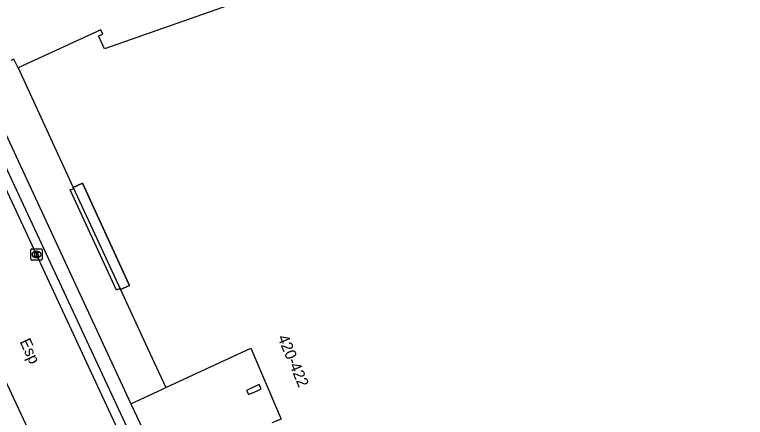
# Model space of a CAD drawing. Extents: x 161389 to 162585, y 388479 to 389761.
# Drawn here: x 162015.4 to 162080.2, y 388829.4 to 388865.1 of the extents above; entities that cross this region are included whole.
import ezdxf

# ---------------------------------------------------------------- set-up
doc = ezdxf.new("R2010")
doc.units = 0
for name, color, linetype in [('IMGEO_Groenvoorziening', 7, 'Continuous'), ('IMGEO_Kolk', 7, 'Continuous'), ('IMGEO_Openbare_ruimte_label', 7, 'Continuous'), ('IMGEO_Pand', 7, 'Continuous'), ('IMGEO_Pand_nummerreeks', 7, 'Continuous'), ('IMGEO_Pand_overbouw', 7, 'Continuous'), ('IMGEO_Rijbaan_lokaal_gesloten', 7, 'Continuous'), ('IMGEO_Voetpad_open', 7, 'Continuous')]:
    doc.layers.add(name, color=color, linetype=linetype)

msp = doc.modelspace()

# ---------------------------------------------------------------- linework, layer by layer
at = {"layer": 'IMGEO_Groenvoorziening'}
for points in [[(162015.754, 388860.392), (162015.389, 388861.182), (162015.139, 388861.066)], [(162024.832, 388840.744), (162024.788, 388840.84), (162024.491, 388840.692), (162020.384, 388849.595), (162020.686, 388849.713), (162020.642, 388849.809)]]:
    msp.add_lwpolyline(points, dxfattribs=at)
at = {"layer": 'IMGEO_Kolk'}
for p, q in [((162016.891, 388843.437), (162016.891, 388844.289)), ((162016.966, 388844.363), (162017.818, 388844.363)), ((162017.892, 388844.289), (162017.892, 388843.437)), ((162017.402, 388843.583), (162017.377, 388843.583)), ((162017.379, 388844.143), (162017.404, 388844.143)), ((162017.818, 388843.363), (162016.966, 388843.363))]:
    msp.add_line(p, q, dxfattribs=at)
for points in [[(162016.891, 388843.437), (162016.891, 388844.289)], [(162016.966, 388844.363), (162017.818, 388844.363)], [(162017.892, 388844.289), (162017.892, 388843.437)], [(162017.212, 388844.063), (162017.335, 388844.063), (162017.335, 388843.912), (162017.465, 388844.063), (162017.629, 388844.063), (162017.483, 388843.912), (162017.636, 388843.663), (162017.484, 388843.663), (162017.399, 388843.827), (162017.335, 388843.76), (162017.335, 388843.663), (162017.212, 388843.663), (162017.212, 388844.063)], [(162017.818, 388843.363), (162016.966, 388843.363)]]:
    msp.add_lwpolyline(points, dxfattribs=at)
for centre, start, end in [((162016.968, 388844.287), 91.55205, 178.44795), ((162016.968, 388844.287), 91.55205, 178.44795), ((162017.816, 388844.287), 1.55205, 88.44795), ((162017.816, 388844.287), 1.55205, 88.44795), ((162016.968, 388843.439), 181.55205, 268.44795), ((162016.968, 388843.439), 181.55205, 268.44795), ((162017.816, 388843.439), 271.55205, 358.44795), ((162017.816, 388843.439), 271.55205, 358.44795)]:
    msp.add_arc(centre, 0.0765, start, end, dxfattribs=at)
for centre, major_axis, ratio, start_param, end_param in [((162017.378, 388843.863), (-0.387, 0.002), 0.722429, 4.712389, 7.853982), ((162017.403, 388843.863), (-0.39, 0.002), 0.717154, 1.570796, 4.712389)]:
    msp.add_ellipse(centre, major_axis=major_axis, ratio=ratio, start_param=start_param, end_param=end_param, dxfattribs=at)
at = {"layer": 'IMGEO_Pand'}
for points in [[(162103.725, 388829.704), (162094.499, 388851.664), (162092.944, 388855.366), (162107.787, 388861.603), (162096.812, 388887.735), (162081.552, 388882.482), (162023.417, 388862.083), (162022.89, 388863.239), (162023.258, 388863.399), (162023.087, 388863.771), (162015.754, 388860.392)], [(162015.754, 388860.392), (162020.642, 388849.809)], [(162020.642, 388849.809), (162021.451, 388850.176), (162025.587, 388841.238), (162025.64, 388841.124), (162024.832, 388840.744)], [(162024.832, 388840.744), (162027.227, 388835.569), (162028.853, 388832.057)], [(162028.853, 388832.057), (162036.403, 388835.564), (162039.082, 388829.266), (162038.244, 388828.934)], [(162036.941, 388831.789), (162037.302, 388831.956), (162037.131, 388832.328), (162036.018, 388831.815), (162036.141, 388831.55), (162036.19, 388831.443), (162036.941, 388831.789)]]:
    msp.add_lwpolyline(points, dxfattribs=at)
at = {"layer": 'IMGEO_Pand_overbouw'}
msp.add_lwpolyline([(162024.832, 388840.744), (162025.64, 388841.124), (162025.587, 388841.238), (162021.451, 388850.176), (162020.642, 388849.809)], close=True, dxfattribs=at)
at = {"layer": 'IMGEO_Rijbaan_lokaal_gesloten'}
for points in [[(161997.535, 388869.23), (162000, 388863.953), (162024.808, 388810.847)], [(162028.29, 388820.387), (162025.739, 388825.856), (162017.391, 388843.863), (162011.069, 388857.378)]]:
    msp.add_lwpolyline(points, dxfattribs=at)
at = {"layer": 'IMGEO_Voetpad_open'}
for points in [[(162012.911, 388858.215), (162025.764, 388830.627)], [(162029.065, 388820.712), (162011.813, 388857.716)], [(162025.764, 388830.627), (162028.555, 388831.919), (162028.853, 388832.057)], [(162025.764, 388830.627), (162027.252, 388827.432)]]:
    msp.add_lwpolyline(points, dxfattribs=at)

# ---------------------------------------------------------------- texts
at = {"layer": 'IMGEO_Openbare_ruimte_label'}
msp.add_text('Esp', height=1, rotation=295.02728, dxfattribs=at).set_placement((162015.874, 388836.137))
at = {"layer": 'IMGEO_Pand_nummerreeks'}
msp.add_text('420-422', height=1, rotation=293.0436, dxfattribs=at).set_placement((162038.74, 388836.507))

doc.saveas('drawing.dxf')
